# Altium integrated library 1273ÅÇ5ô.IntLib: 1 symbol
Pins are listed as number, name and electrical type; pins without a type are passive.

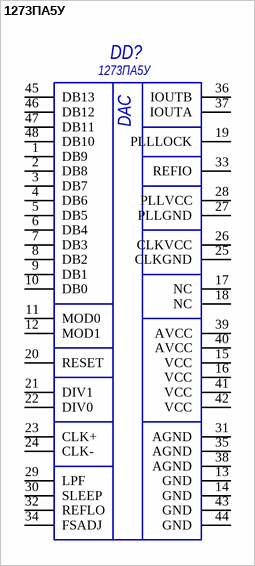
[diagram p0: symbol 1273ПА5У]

## 1273ПА5У
designator DD?
Manufacturer: АО"НИИЭТ"; Library Developer: Aleksey Voronov   (aleksey.voronov.36@yandex.ru)
footprint 5133.48-3
pins: 1 DB9, 2 DB8, 3 DB7, 4 DB6, 5 DB5, 6 DB4, 7 DB3, 8 DB2, 9 DB1, 10 DB0, 11 MOD0, 12 MOD1, 13 GND, 14 GND, 15 VCC, 16 VCC, 17 NC, 18 NC, 19 PLLLOCK, 20 RESET, 21 DIV1, 22 DIV0, 23 CLK+, 24 CLK-, 25 CLKGND, 26 CLKVCC, 27 PLLGND, 28 PLLVCC, 29 LPF, 30 SLEEP, 31 AGND, 32 REFLO, 33 REFIO, 34 FSADJ, 35 AGND, 36 IOUTB, 37 IOUTA, 38 AGND, 39 AVCC, 40 AVCC, 41 VCC, 42 VCC, 43 GND, 44 GND, 45 DB13, 46 DB12, 47 DB11, 48 DB10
